// Mitsubishi GX Works2 project: 5.连锁控制   PLC: FX3U/FX3UC

PROGRAM MAIN
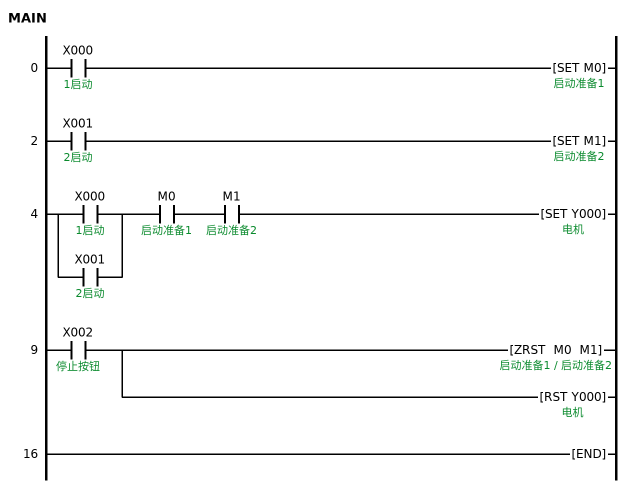
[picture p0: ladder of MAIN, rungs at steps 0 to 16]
0     LD      X000  ; 1启动
      SET     M0  ; 启动准备1
2     LD      X001  ; 2启动
      SET     M1  ; 启动准备2
4     LD      X000  ; 1启动
      OR      X001  ; 2启动
      AND     M0  ; 启动准备1
      AND     M1  ; 启动准备2
      SET     Y000  ; 电机
9     LD      X002  ; 停止按钮
      ZRST    M0 M1
      RST     Y000  ; 电机
16    END
END_PROGRAM
